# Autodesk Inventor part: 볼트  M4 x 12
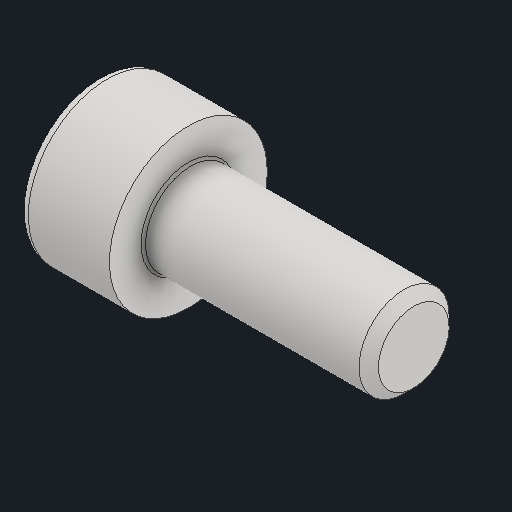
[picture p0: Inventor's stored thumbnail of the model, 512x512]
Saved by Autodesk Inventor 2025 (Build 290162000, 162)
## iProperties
Created: 2025-08
Part Number: 볼트  M4 x 12
Material: 스테인리스강
Description: 6각머리 태핑 나사
Document SubType Name: Modeling
Designer: infra023
Density: 8.08 g/cm^3
Appearance: 기본값
Author: jhkim
Sending System: Autodesk Inventor 2026
Preprocessor: ST-DEVELOPER v20.1
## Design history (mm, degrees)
feature "Solid1"
node "솔리드1"
